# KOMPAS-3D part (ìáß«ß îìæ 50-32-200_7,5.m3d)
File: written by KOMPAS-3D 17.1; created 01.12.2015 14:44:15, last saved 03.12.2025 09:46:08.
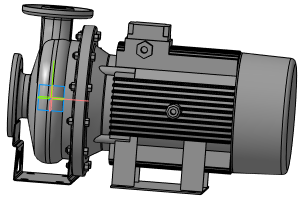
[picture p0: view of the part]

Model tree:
1. Операция без истории:4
